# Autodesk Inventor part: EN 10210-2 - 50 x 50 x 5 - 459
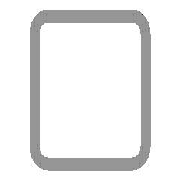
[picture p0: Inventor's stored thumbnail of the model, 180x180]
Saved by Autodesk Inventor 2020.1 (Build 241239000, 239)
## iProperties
IsCustomPart: 1
_CCFamilyMember: 16
_CCFamilyDisplayName: DIN EN 10210-2 (USAS B17.1 quadratisch) - Rohrleitung — In Klammern angegebene Größen wurden aufgehoben
_FrameMemberDoc: Frame Member File
_Version: 15.0.0
_GetPNFromCC: 1
Created: 2019-01
Part Number: EN 10210-2 - 50 x 50 x 5 - 459
Material: Stahl, weich
Description: Rohrleitung
Document SubType Name: Modeling
Standard: DIN
Designer: lutzd
Standard Revision: 2006-07
Standards Organization: DIN
Language: de-DE
Size Designation: 50 x 50 x 5
Categories: <MemberInstance><Categories><Category DisplayName="Profile" InternalName="089c4875-fa83-4c05-b084-43b9cc11f5ed" Mnemonic="GRDR"><CategoryParameter DisplayName="
Stock Number: 50 x 50 x 5
Mass: 3146.18 g
Surface Area: 1571.36 cm^2
Volume: 400.787 cm^3
Density: 7.85 g/cm^3
Appearance: Halbpoliert
G_W: 50,000 mm
G_H: 50,000 mm
DocNumber: ADSK-014206
Folder: .
Dimensions: 50x50x459 mm
Mass: 3,146 kg
+F6AE9326-A186-43DD-A142-1AF7765A0DBA+SCHNITTDETAIL1: Schnittwinkel 90,00 grd
+15E2AB1B-B8F7-44BF-871D-A7489F932D77+SCHNITTDETAIL2: Schnittwinkel 90,00 grd
G_L: 459,000 mm
Title: Profil-Bauteil
Author: lutzd
Revision Number: -
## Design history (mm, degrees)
node "Startebene"
node "Endebene"
sketch "Skizze"
  geometry: L1 (-25, -17.5)-(-25, 17.5); L2 (-17.5, 25)-(17.5, 25); L3 (25, 17.5)-(25, -17.5); L4 (17.5, -25)-(-17.5, -25); L5 (-15, 20)-(15, 20); L6 (20, 15)-(20, -15); L7 (15, -20)-(-15, -20); L8 (-20, -15)-(-20, 15); L9 (0, 37.175)-(0, -37.175) reference; L10 (-37.175, 0)-(37.175, 0) reference; A1 r 7.5 centre (-17.5, -17.5) between (-25, -17.5) and (-17.5, -25); A2 r 7.5 centre (-17.5, 17.5) between (-17.5, 25) and (-25, 17.5); A3 r 7.5 centre (17.5, 17.5) between (25, 17.5) and (17.5, 25); A4 r 7.5 centre (17.5, -17.5) between (17.5, -25) and (25, -17.5); A5 r 5 centre (-15, -15) between (-20, -15) and (-15, -20); A6 r 5 centre (-15, 15) between (-15, 20) and (-20, 15); A7 r 5 centre (15, 15) between (20, 15) and (15, 20); A8 r 5 centre (15, -15) between (15, -20) and (20, -15)
  constraints: 16 end point, 16 point on circle, 16 tangent, 8 centre point, 6 equal radius, 4 parallel, 2 perpendicular, 2 other
  dimensions: "d7" = 7.5 radius of A1 (= G_IR); "d10" = 50 distance between parallel lines of L2 L4 (= G_H); "d11" = 50 distance between parallel lines of L1 L3 (= G_W); "d12" = 5 distance between parallel lines of L3 L6 (= G_T); "d15" = 25 distance between parallel lines of L2 L10 (= 0.5 x d10); "d16" = 25 distance between parallel lines of L9 L3 (= 0.5 x d11); "d19" = 5 radius of A5 (= G_T); "d20" = 5 distance between parallel lines of L4 L7 (= G_T)
extrude "Körper" new body sketch "Skizze" stored distance "d3" = 459 (= G_L); taper "d4" = 0 deg
node "Driven Length"
  sketch "Sketch3"
    geometry: L1 (0, 0)-(10, 0) reference
    constraints: 2 end point, 1 horizontal
  workplane "Work Plane3"
  sketch "Sketch4"
    geometry: L1 (-2, 50)-(12, 50) reference; L2 (-2, 509)-(12, 509) reference
    dimensions: "d18" = 459 distance between parallel lines of L1 L2 (derived)
workplane "Arbeitsebene4"
feature "Trennen1"
workplane "Arbeitsebene5"
feature "Trennen2"
body "Solid1"
other parameters: "G_W" = 50 [user parameter; used in 1 equation term], "G_H" = 50 [user parameter; used in 1 equation term], "G_T" = 5 [user parameter; used in 3 equation terms], "G_IR" = 7.5 [user parameter; used in 1 equation term], "G_L" = 459 (= d18) [user parameter; used in 1 equation term], "d14" = 509 (= G_OFFSET_END + B_L), "B_L" = 559 [user parameter; used in 1 equation term], "d17" = 90 deg
